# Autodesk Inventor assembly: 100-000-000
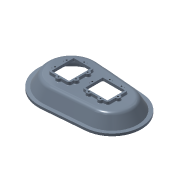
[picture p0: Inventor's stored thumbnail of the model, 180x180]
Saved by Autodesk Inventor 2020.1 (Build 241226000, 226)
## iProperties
Created: 2010-02
Part Number: 100-000-000
Document SubType Name: Assembly
Designer: F.Stasiak
Manager: www.cadconsulting.pl
Company: Fabian Stasiak CAD Consulting
Author: F.Stasiak
Subject: Zbiór ćwiczeń. Autodesk Inventor 2020. Kurs podstawowy
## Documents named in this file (2)
- C:\2020_Kurs_podstawowy\R6 Zespoły\iMate\100-000-000.iam
- C:\2020_Kurs_podstawowy\R6 Zespoły\iMate\100-100-001.ipt
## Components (1 placed, 1 different names)
1. 100-100-001:1
